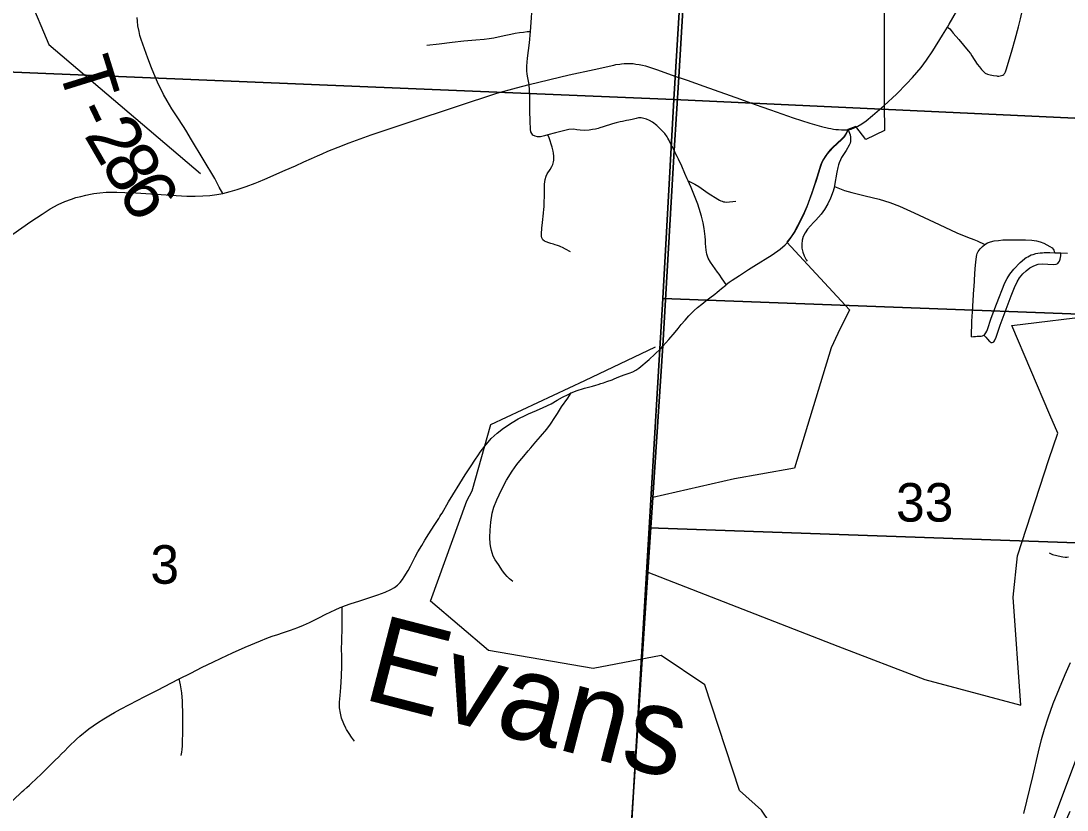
# Model space of a CAD drawing. Extents: x 21.4 to 65.3, y 4 to 26.
# Drawn here: x 25.81 to 26.947, y 22.714 to 23.571 of the extents above; entities that cross this region are included whole.
import ezdxf

# ---------------------------------------------------------------- set-up
doc = ezdxf.new("R2010")
doc.units = 0
for name, color, linetype in [('Default', 7, 'Continuous'), ('GM_X_City_Street', 7, 'Continuous'), ('GM_X_County_Road', 7, 'Continuous'), ('GM_X_Major_River', 7, 'Continuous'), ('GM_X_Minor_River', 7, 'Continuous'), ('GM_X_Minor_River_Text', 7, 'Continuous'), ('GM_X_Section', 7, 'Continuous'), ('GM_X_Section_Text', 7, 'Continuous'), ('GM_X_State_Route', 7, 'Continuous'), ('GM_X_Township_Road', 7, 'Continuous'), ('GM_X_Township_Road_Text', 7, 'Continuous')]:
    doc.layers.add(name, color=color, linetype=linetype)

msp = doc.modelspace()

# ---------------------------------------------------------------- linework, layer by layer
at = {"layer": 'Default'}
for points in [[(26.3906, 21.3613), (26.4573, 22.45), (26.4915, 22.9722), (26.4968, 23.0532), (26.5076, 23.2181), (26.5201, 23.4302), (26.5253, 23.5099), (26.571, 24.2838), (26.5714, 24.2916), (26.5716, 24.3007), (26.5721, 24.3116), (26.5728, 24.3278), (26.5729, 24.3421), (26.5729, 24.3464), (26.5731, 24.3575), (26.5731, 24.358), (26.5731, 24.3616), (26.5731, 24.3659), (26.5732, 24.3694), (26.5734, 24.3737), (26.5741, 24.3781), (26.6018, 24.8542), (23.5473, 24.8542), (23.5473, 20.5568)], [(29.9103, 24.8542), (26.6018, 24.8542), (26.5741, 24.3781), (26.5734, 24.3737), (26.5732, 24.3694), (26.5731, 24.3659), (26.5731, 24.3616), (26.5731, 24.358), (26.5731, 24.3575), (26.5729, 24.3464), (26.5729, 24.3421), (26.5728, 24.3278), (26.5721, 24.3116), (26.5716, 24.3007), (26.5714, 24.2916), (26.571, 24.2838), (26.5253, 23.5099), (26.5201, 23.4302), (26.5076, 23.2181), (26.4968, 23.0532), (26.4915, 22.9722), (26.4573, 22.45), (26.3906, 21.3613)], [(26.7486, 23.7813), (26.7481, 23.4797), (26.7485, 23.4518), (26.7284, 23.4422), (26.7174, 23.4563), (26.7088, 23.4531), (26.7075, 23.45), (26.706, 23.4473), (26.7052, 23.446), (26.7042, 23.4448), (26.7021, 23.4428), (26.6922, 23.4335), (26.6896, 23.4308), (26.6866, 23.4272), (26.6841, 23.4237), (26.6822, 23.4206), (26.6803, 23.4168), (26.6788, 23.4128), (26.677, 23.4068), (26.6744, 23.3986), (26.6695, 23.3839), (26.6644, 23.37), (26.6603, 23.3604), (26.6571, 23.354), (26.6542, 23.3482), (26.6505, 23.3415), (26.6467, 23.336), (26.6426, 23.3306), (26.7105, 23.2572), (26.6979, 23.2313), (26.6908, 23.216), (26.6508, 23.0851), (26.6144, 23.0787), (26.5855, 23.0736), (26.4968, 23.0532), (26.4915, 22.9722), (26.698, 22.8919), (26.7924, 22.8556), (26.8965, 22.8277), (26.8883, 22.9449), (26.8931, 22.9901), (26.9271, 23.0947), (26.9369, 23.1232), (26.928, 23.1431), (26.8869, 23.24), (26.9821, 23.2516)]]:
    msp.add_lwpolyline(points, dxfattribs=at)
at = {"layer": 'GM_X_City_Street'}
for points in [[(26.877, 23.5119), (26.8781, 23.5127), (26.8787, 23.5134), (26.8794, 23.5143), (26.88, 23.5158), (26.8808, 23.5179), (26.8823, 23.5225), (26.8873, 23.5397), (26.8906, 23.5512), (26.8943, 23.5645), (26.8963, 23.5731), (26.8994, 23.5875), (26.9034, 23.6082), (26.9059, 23.6222), (26.9076, 23.63), (26.9088, 23.6349), (26.9105, 23.6409), (26.9111, 23.6426), (26.9122, 23.6448), (26.9152, 23.6491)], [(26.8171, 23.5643), (26.8194, 23.5622), (26.8209, 23.5607), (26.8233, 23.5578), (26.8294, 23.5507), (26.8345, 23.5446), (26.8396, 23.5384), (26.8419, 23.5354), (26.8435, 23.533), (26.8493, 23.5239), (26.8516, 23.5209), (26.8538, 23.5182), (26.8556, 23.5162), (26.8578, 23.5143), (26.8605, 23.5131), (26.8633, 23.5122), (26.8669, 23.5115), (26.8705, 23.5112), (26.8715, 23.5111), (26.8726, 23.5111), (26.8741, 23.5113), (26.8755, 23.5115), (26.877, 23.5119)], [(26.709, 23.4526), (26.7112, 23.4471), (26.7116, 23.4448), (26.7118, 23.4422), (26.7116, 23.44), (26.7111, 23.4381), (26.7102, 23.436), (26.7068, 23.4303), (26.702, 23.4226), (26.7007, 23.4199), (26.6994, 23.4169), (26.6985, 23.4146), (26.6978, 23.4118), (26.6967, 23.4068), (26.6943, 23.3921), (26.6941, 23.3911), (26.6927, 23.3861), (26.69, 23.3785), (26.687, 23.3724), (26.6833, 23.366), (26.6797, 23.361), (26.6769, 23.3577), (26.674, 23.3545), (26.6714, 23.3518), (26.6651, 23.3449), (26.6623, 23.3408), (26.6603, 23.3369), (26.6591, 23.3328), (26.6586, 23.3284), (26.6588, 23.3241), (26.6597, 23.3198), (26.6612, 23.3158), (26.6635, 23.3114), (26.6644, 23.3101)], [(26.6941, 23.3911), (26.6998, 23.3889), (26.705, 23.3868), (26.7132, 23.3844), (26.7275, 23.3811), (26.7429, 23.3772), (26.7545, 23.3736), (26.7647, 23.3696), (26.7809, 23.3624), (26.8081, 23.3497), (26.827, 23.3409), (26.8389, 23.336), (26.8456, 23.3335), (26.8491, 23.3321), (26.8576, 23.3281), (26.8604, 23.3299), (26.8636, 23.3311), (26.8678, 23.3321), (26.8724, 23.3326), (26.8772, 23.333), (26.8901, 23.3332), (26.9019, 23.333), (26.9087, 23.3327), (26.9136, 23.3321), (26.9178, 23.3311), (26.9218, 23.3296), (26.9283, 23.326), (26.9306, 23.3244), (26.9319, 23.3229), (26.9325, 23.3218), (26.933, 23.3206), (26.9335, 23.3192)], [(26.8432, 23.2277), (26.8431, 23.2331), (26.8434, 23.2393), (26.8434, 23.2418), (26.8436, 23.2448), (26.8441, 23.2548), (26.8449, 23.2672), (26.8457, 23.2796), (26.8458, 23.2821), (26.8468, 23.2962), (26.8472, 23.3018), (26.8479, 23.3094), (26.8481, 23.3119), (26.8485, 23.3152), (26.8489, 23.317), (26.8494, 23.3184), (26.8503, 23.3203), (26.8526, 23.3235), (26.8549, 23.3259), (26.8576, 23.3281)], [(26.8432, 23.2277), (26.8453, 23.2281), (26.8473, 23.2283), (26.8491, 23.2284), (26.852, 23.2285), (26.8537, 23.2286), (26.855, 23.2289), (26.8563, 23.2296), (26.8571, 23.23), (26.858, 23.2309), (26.8588, 23.232), (26.8597, 23.2338), (26.8604, 23.2359), (26.8644, 23.2482), (26.8702, 23.2633), (26.8793, 23.2863), (26.8819, 23.2913), (26.8849, 23.296), (26.8892, 23.3013), (26.896, 23.3085), (26.8982, 23.3104), (26.901, 23.3128), (26.9025, 23.3138), (26.9041, 23.3148), (26.906, 23.3158), (26.908, 23.3167), (26.91, 23.3174), (26.9128, 23.3182), (26.9151, 23.3186), (26.9177, 23.319), (26.9201, 23.3192), (26.922, 23.3193), (26.9252, 23.3194), (26.9282, 23.3194), (26.9335, 23.3192), (26.94, 23.3189), (26.9474, 23.3187)], [(26.8563, 23.2296), (26.8585, 23.2273), (26.8603, 23.2253), (26.8628, 23.2226), (26.8634, 23.2222), (26.8642, 23.2218), (26.8649, 23.2216), (26.8656, 23.2216), (26.8665, 23.2219), (26.8674, 23.2225), (26.8679, 23.2233), (26.8684, 23.2243), (26.8698, 23.2273), (26.8741, 23.2403), (26.8806, 23.2577), (26.8862, 23.2722), (26.8899, 23.2814), (26.8928, 23.2876), (26.8954, 23.2918), (26.8989, 23.2962), (26.9024, 23.2996), (26.9064, 23.3027), (26.9107, 23.305), (26.9154, 23.3066), (26.9204, 23.3071), (26.926, 23.3069), (26.9322, 23.3064), (26.9352, 23.3068), (26.9369, 23.3076), (26.9377, 23.3084), (26.9387, 23.3099), (26.9394, 23.3122), (26.94, 23.3159), (26.94, 23.3189)]]:
    msp.add_lwpolyline(points, dxfattribs=at)
at = {"layer": 'GM_X_County_Road'}
for points in [[(26.6428, 23.33), (26.6469, 23.3354), (26.6507, 23.341), (26.6544, 23.3476), (26.6573, 23.3535), (26.6605, 23.3598), (26.6646, 23.3695), (26.6698, 23.3834), (26.6746, 23.3981), (26.6772, 23.4063), (26.679, 23.4122), (26.6805, 23.4163), (26.6824, 23.42), (26.6843, 23.4232), (26.6868, 23.4266), (26.6898, 23.4303), (26.6924, 23.433), (26.7023, 23.4422), (26.7044, 23.4443), (26.7054, 23.4455), (26.7062, 23.4468), (26.7077, 23.4495), (26.709, 23.4526)], [(26.5078, 23.2176), (26.5143, 23.2248), (26.521, 23.2327), (26.5243, 23.2369), (26.5278, 23.2412), (26.5319, 23.246), (26.536, 23.2506), (26.5393, 23.254), (26.5417, 23.2563), (26.5456, 23.2596), (26.5501, 23.2633), (26.5546, 23.2668), (26.559, 23.27), (26.5643, 23.2743), (26.5667, 23.2763), (26.569, 23.2783), (26.5714, 23.2802), (26.5761, 23.284), (26.5767, 23.2845), (26.5799, 23.287), (26.5832, 23.2894), (26.591, 23.2945), (26.6009, 23.3009), (26.6067, 23.3044), (26.6266, 23.317), (26.6351, 23.323), (26.6407, 23.3278), (26.6428, 23.33)], [(25.8016, 22.7243), (25.8118, 22.7338), (25.8137, 22.7355), (25.8168, 22.7384), (25.8196, 22.7408), (25.8228, 22.7438), (25.826, 22.7467), (25.8282, 22.7488), (25.8314, 22.7517), (25.8349, 22.7552), (25.8376, 22.7578), (25.841, 22.7613), (25.8441, 22.7643), (25.8476, 22.7679), (25.8512, 22.7713), (25.8545, 22.7749), (25.8581, 22.7783), (25.8615, 22.7819), (25.8652, 22.7852), (25.8683, 22.7883), (25.871, 22.7908), (25.8746, 22.7941), (25.8842, 22.8021), (25.8935, 22.8085), (25.9006, 22.8128), (25.9078, 22.8173), (25.912, 22.8197), (25.9187, 22.8234), (25.9283, 22.8286), (25.945, 22.8371), (25.959, 22.844), (25.9816, 22.8558), (25.9825, 22.8562), (25.9951, 22.8623), (26.0074, 22.8689), (26.0188, 22.8745), (26.0279, 22.8788), (26.0402, 22.8846), (26.0541, 22.8908), (26.0707, 22.8977), (26.0777, 22.9004), (26.0834, 22.9025), (26.0895, 22.9046), (26.0945, 22.9063), (26.1033, 22.9091), (26.1114, 22.912), (26.1173, 22.9146), (26.1239, 22.9174), (26.1297, 22.9204), (26.1349, 22.9231), (26.141, 22.9261), (26.1471, 22.9292), (26.1519, 22.9314), (26.1573, 22.9338), (26.1595, 22.9346), (26.1621, 22.9355), (26.1691, 22.938), (26.1777, 22.9408), (26.185, 22.9432), (26.198, 22.9474), (26.206, 22.9505), (26.2122, 22.9533), (26.2164, 22.9557), (26.2196, 22.9582), (26.2224, 22.961), (26.2248, 22.9642), (26.2269, 22.9671), (26.2311, 22.9739), (26.2337, 22.9788), (26.2387, 22.9888), (26.2417, 22.9943), (26.2458, 23.0012), (26.2494, 23.007), (26.2537, 23.0139), (26.2595, 23.0227), (26.2644, 23.0306), (26.2657, 23.0327), (26.2666, 23.0343), (26.2679, 23.0363), (26.275, 23.0486), (26.2795, 23.056), (26.2874, 23.0685), (26.293, 23.078), (26.2995, 23.0878), (26.3037, 23.094), (26.3074, 23.0997), (26.3095, 23.1027), (26.3144, 23.1092), (26.3214, 23.1172), (26.3278, 23.1232), (26.3347, 23.1286), (26.344, 23.1349), (26.3505, 23.1387), (26.359, 23.1428), (26.3618, 23.144), (26.3662, 23.146), (26.3704, 23.1476), (26.3779, 23.1511), (26.3866, 23.1552), (26.393, 23.1589), (26.3989, 23.1623), (26.405, 23.1653), (26.4081, 23.1668), (26.4094, 23.1674), (26.4138, 23.1691), (26.4226, 23.172), (26.4314, 23.1743), (26.4351, 23.1752), (26.4376, 23.176), (26.4405, 23.177), (26.4434, 23.1779), (26.4469, 23.1792), (26.4526, 23.1812), (26.4549, 23.1822), (26.4601, 23.1842), (26.4658, 23.1864), (26.4711, 23.1884), (26.4753, 23.1899), (26.4784, 23.1916), (26.4816, 23.1936), (26.493, 23.2033), (26.5051, 23.2146), (26.5078, 23.2176)]]:
    msp.add_lwpolyline(points, dxfattribs=at)
at = {"layer": 'GM_X_Major_River'}
msp.add_lwpolyline([(27.3721, 23.3957), (27.3499, 23.3785), (27.3039, 23.3339), (27.2682, 23.2939), (27.2227, 23.2357), (27.187, 23.179), (27.1419, 23.1192), (27.1141, 23.0781), (27.1024, 23.0556), (27.062, 22.9659), (27.006, 22.873), (26.973, 22.8129), (26.9266, 22.6893), (26.8772, 22.5703), (26.8597, 22.503), (26.8575, 22.4909), (26.8322, 22.3833), (26.828, 22.3063), (26.8227, 22.1096)], dxfattribs=at)
at = {"layer": 'GM_X_Minor_River'}
for points in [[(25.8194, 23.5963), (25.8409, 23.5452), (26.0056, 23.4051)], [(26.8808, 22.5795), (26.8755, 22.5813), (26.827, 22.5456), (26.8241, 22.5695), (26.7757, 22.6089), (26.7538, 22.6), (26.746, 22.5889), (26.6714, 22.63), (26.6149, 22.7137), (26.5911, 22.7352), (26.5535, 22.8498), (26.506, 22.8817), (26.4322, 22.8677), (26.3184, 22.8872), (26.2554, 22.9406), (26.295, 23.0495), (26.3006, 23.0605), (26.3209, 23.1324), (26.4231, 23.1804), (26.4997, 23.2168)]]:
    msp.add_lwpolyline(points, dxfattribs=at)
at = {"layer": 'GM_X_Section'}
for points in [[(26.5825, 24.5101), (26.5198, 23.4854), (25.4788, 23.5287), (25.4893, 23.7114), (25.5145, 24.1345), (25.5389, 24.555)], [(26.5825, 24.5101), (27.6091, 24.4648), (27.5486, 23.5443), (27.5415, 23.5386), (27.5313, 23.5298), (27.5214, 23.5207), (27.5097, 23.5112), (27.4908, 23.4937), (27.4682, 23.4724), (27.4508, 23.456), (27.444, 23.4496), (27.4376, 23.4427), (26.5198, 23.4854)], [(25.4788, 23.5287), (26.5198, 23.4854), (26.5078, 23.2694), (26.4931, 23.0203), (26.4742, 22.7032), (26.4597, 22.4573), (25.4085, 22.5025), (25.4647, 23.2936)], [(26.5198, 23.4854), (27.4376, 23.4427), (27.4251, 23.4336), (27.4176, 23.4283), (27.3873, 23.4073), (27.3756, 23.3925), (27.3511, 23.3712), (27.3311, 23.3548), (27.311, 23.3339), (27.2963, 23.3195), (27.285, 23.3081), (27.2756, 23.2944), (27.2654, 23.2773), (27.256, 23.2621), (27.2435, 23.2454), (27.2404, 23.2418), (26.5078, 23.2694)], [(27.2404, 23.2418), (27.2326, 23.2325), (27.2118, 23.2108), (27.1948, 23.1911), (27.1767, 23.1683), (27.1658, 23.1508), (27.1552, 23.1356), (27.1466, 23.1231), (27.1394, 23.1121), (27.133, 23.0999), (27.1266, 23.0851), (27.124, 23.0768), (27.1153, 23.0642), (27.1059, 23.0475), (27.098, 23.0255), (27.0935, 23.0107), (27.0913, 22.9992), (26.4931, 23.0203), (26.5078, 23.2694)]]:
    msp.add_lwpolyline(points, close=True, dxfattribs=at)
msp.add_lwpolyline([(26.9498, 22.7121), (26.9438, 22.698), (26.9387, 22.6861), (26.4742, 22.7032), (26.4931, 23.0203), (27.0913, 22.9992)], dxfattribs=at)
at = {"layer": 'GM_X_State_Route'}
for points in [[(26.7483, 23.4792), (26.7616, 23.4915), (26.773, 23.5031), (26.779, 23.5094), (26.7838, 23.515), (26.7883, 23.5203), (26.7943, 23.5283), (26.8012, 23.5383), (26.8117, 23.5553), (26.8171, 23.5643), (26.8188, 23.5673), (26.8322, 23.5904)], [(26.0687, 23.3962), (26.0754, 23.399), (26.0975, 23.4089), (26.1086, 23.4137), (26.1179, 23.4178), (26.1262, 23.4215), (26.1327, 23.4243), (26.1378, 23.4266), (26.144, 23.4293), (26.155, 23.4337), (26.1669, 23.4386), (26.1908, 23.4472), (26.231, 23.4605), (26.2846, 23.4785), (26.3276, 23.4924), (26.3489, 23.4984), (26.3627, 23.502), (26.406, 23.5122), (26.433, 23.5183), (26.4544, 23.523), (26.4568, 23.5235), (26.4609, 23.5241), (26.4628, 23.5243), (26.4659, 23.5246), (26.4693, 23.5248), (26.4725, 23.5247), (26.4754, 23.5246), (26.4786, 23.5241), (26.4821, 23.5237), (26.4856, 23.5229), (26.4889, 23.522), (26.4987, 23.5189), (26.502, 23.5178), (26.5249, 23.5096), (26.5255, 23.5094)], [(26.5255, 23.5094), (26.5341, 23.5064), (26.5524, 23.4999), (26.592, 23.4858), (26.603, 23.4819), (26.6153, 23.4775), (26.6246, 23.4742), (26.6493, 23.4658), (26.6674, 23.4598), (26.6801, 23.4563), (26.6877, 23.4544), (26.6904, 23.4539), (26.693, 23.4535), (26.6958, 23.4531), (26.6986, 23.4529), (26.7017, 23.4527), (26.7052, 23.4525), (26.709, 23.4526)], [(26.7285, 23.4623), (26.7356, 23.4681), (26.7483, 23.4792)], [(26.709, 23.4526), (26.7122, 23.4535), (26.7156, 23.4548), (26.7196, 23.4566), (26.724, 23.4591), (26.7285, 23.4623)], [(25.8018, 23.3394), (25.8212, 23.353), (25.8334, 23.3611), (25.8421, 23.3668), (25.851, 23.3714), (25.8583, 23.3747), (25.8653, 23.3773), (25.8702, 23.379), (25.8754, 23.3803), (25.8808, 23.3816), (25.8859, 23.3826), (25.8898, 23.3833), (25.8962, 23.3842), (25.9029, 23.3848), (25.908, 23.3849), (25.9146, 23.385), (25.9233, 23.3847), (25.9352, 23.3841), (25.9791, 23.3812), (25.9907, 23.3806), (25.9998, 23.3805), (26.008, 23.3808), (26.0158, 23.3814), (26.0233, 23.3823), (26.0297, 23.3835), (26.0378, 23.3855), (26.0454, 23.3877), (26.0551, 23.391), (26.0649, 23.3947), (26.0687, 23.3962)], [(26.8999, 22.7099), (26.9096, 22.7504), (26.9158, 22.777), (26.9193, 22.7903), (26.9225, 22.8017), (26.9264, 22.8141), (26.9319, 22.8294), (26.9386, 22.8461), (26.9449, 22.861), (26.9507, 22.8741)]]:
    msp.add_lwpolyline(points, dxfattribs=at)
at = {"layer": 'GM_X_Township_Road'}
for points in [[(26.3627, 23.502), (26.3608, 23.5108), (26.3604, 23.5136), (26.3601, 23.5165), (26.3601, 23.5192), (26.3602, 23.5219), (26.3609, 23.5303), (26.3629, 23.5471), (26.364, 23.5595), (26.365, 23.5743), (26.3658, 23.586), (26.3667, 23.6027), (26.3677, 23.6212)], [(25.9896, 23.4521), (25.987, 23.4564), (25.9802, 23.4668), (25.9745, 23.4756), (25.9693, 23.4841), (25.9654, 23.4911), (25.9589, 23.5045), (25.9566, 23.5096), (25.9523, 23.5199), (25.9484, 23.5303), (25.9465, 23.5355), (25.9412, 23.5507), (25.9398, 23.5552), (25.9388, 23.5595), (25.9376, 23.5656), (25.9371, 23.5706), (25.9368, 23.5745)], [(26.2515, 23.5446), (26.2649, 23.5461), (26.2788, 23.5478), (26.2917, 23.5492), (26.3046, 23.5503), (26.3137, 23.551), (26.319, 23.5517), (26.3242, 23.5526), (26.3355, 23.5551), (26.3392, 23.5559), (26.3427, 23.5567), (26.3472, 23.5575), (26.3521, 23.5583), (26.3565, 23.5588), (26.3605, 23.5593), (26.364, 23.5595)], [(26.5204, 23.4297), (26.5178, 23.4345), (26.5162, 23.4379), (26.5143, 23.4417), (26.5132, 23.4437), (26.5123, 23.4452), (26.5098, 23.4486), (26.5073, 23.4513), (26.5011, 23.4572), (26.4964, 23.461), (26.4933, 23.4629), (26.4901, 23.4643), (26.4873, 23.4651), (26.4844, 23.4656), (26.4815, 23.4655), (26.4787, 23.4649), (26.4746, 23.4639), (26.471, 23.4632), (26.4683, 23.4627), (26.4655, 23.4622), (26.4638, 23.4618), (26.4614, 23.4614), (26.4571, 23.4601), (26.4532, 23.459), (26.4431, 23.4558), (26.4395, 23.4547), (26.4377, 23.4542), (26.4347, 23.4535), (26.4315, 23.4529), (26.4279, 23.4523), (26.4228, 23.452), (26.4178, 23.4523), (26.4143, 23.4528), (26.411, 23.4532), (26.4057, 23.453), (26.3997, 23.4517), (26.3913, 23.4495), (26.3829, 23.4471), (26.3793, 23.446), (26.3749, 23.4452), (26.3716, 23.4451), (26.369, 23.4457), (26.3666, 23.447), (26.3653, 23.4486), (26.3644, 23.4504), (26.3639, 23.4531), (26.3635, 23.4623), (26.3633, 23.4729), (26.3634, 23.4901), (26.3627, 23.502)], [(26.0297, 23.3835), (26.0259, 23.3905), (26.021, 23.3996), (26.0085, 23.4208), (25.9959, 23.4417), (25.9896, 23.4521)], [(26.4074, 23.32), (26.4022, 23.323), (26.3987, 23.3248), (26.3971, 23.3256), (26.3954, 23.3262), (26.3943, 23.3265), (26.3932, 23.3269), (26.3909, 23.3277), (26.3891, 23.3283), (26.3874, 23.3288), (26.3862, 23.3292), (26.3839, 23.3298), (26.381, 23.3309), (26.3793, 23.3318), (26.3775, 23.3333), (26.3762, 23.3353), (26.3759, 23.3371), (26.3758, 23.3395), (26.3765, 23.3457), (26.377, 23.3518), (26.3782, 23.3622), (26.3786, 23.3665), (26.3787, 23.3689), (26.3789, 23.3739), (26.3791, 23.3807), (26.3792, 23.3869), (26.3794, 23.3937), (26.3795, 23.3962), (26.3799, 23.3986), (26.381, 23.4022), (26.3823, 23.405), (26.3854, 23.4096), (26.3873, 23.4128), (26.3883, 23.4151), (26.3888, 23.4165), (26.3891, 23.418), (26.3893, 23.4198), (26.3893, 23.4217), (26.3892, 23.4242), (26.3889, 23.4272), (26.3885, 23.4296), (26.3875, 23.4337), (26.3865, 23.4372), (26.3854, 23.4407), (26.3843, 23.4438), (26.3829, 23.4471)], [(26.5767, 23.2845), (26.5724, 23.2907), (26.569, 23.2957), (26.5672, 23.2982), (26.5597, 23.3089), (26.5572, 23.3133), (26.5556, 23.3175), (26.5547, 23.3218), (26.5543, 23.3293), (26.5541, 23.3329), (26.5538, 23.3366), (26.5535, 23.3396), (26.5527, 23.3456), (26.5515, 23.3516), (26.5498, 23.3588), (26.5473, 23.3671), (26.5458, 23.3718), (26.5422, 23.381), (26.5385, 23.3901), (26.5367, 23.394), (26.5352, 23.3972), (26.5341, 23.3994), (26.5316, 23.4052), (26.5283, 23.413), (26.5247, 23.4208), (26.5234, 23.4236), (26.5217, 23.4269), (26.5204, 23.4297)], [(26.5352, 23.3972), (26.5403, 23.3947), (26.5424, 23.3937), (26.5468, 23.3909), (26.5571, 23.3839), (26.5676, 23.3772), (26.5693, 23.3763), (26.5709, 23.3755), (26.5723, 23.3751), (26.5738, 23.3746), (26.5752, 23.3743), (26.5769, 23.3742), (26.5869, 23.3752)], [(26.3215, 22.9956), (26.3208, 22.9991), (26.3203, 23.0028), (26.3199, 23.0097), (26.3201, 23.0177), (26.3209, 23.0264), (26.3225, 23.0362), (26.3243, 23.0428), (26.3274, 23.0509), (26.3324, 23.0616), (26.338, 23.072), (26.3441, 23.082), (26.3492, 23.0891), (26.3526, 23.0932), (26.3567, 23.0981), (26.3616, 23.1038), (26.3643, 23.1072), (26.3699, 23.1137), (26.375, 23.1197), (26.3816, 23.1274), (26.3858, 23.1328), (26.3904, 23.1402), (26.3932, 23.1446), (26.3977, 23.1517), (26.4044, 23.1613), (26.4081, 23.1668)], [(26.3447, 22.962), (26.3411, 22.9649), (26.3387, 22.9673), (26.3362, 22.9702), (26.3335, 22.9738), (26.3292, 22.9804), (26.3258, 22.9854), (26.3236, 22.9897), (26.3222, 22.9933), (26.3215, 22.9956)], [(26.9274, 22.9932), (26.9289, 22.9923), (26.9311, 22.9915), (26.9406, 22.9893), (26.9424, 22.9889), (26.9449, 22.9885), (26.9467, 22.9886), (26.9485, 22.989)], [(26.1727, 22.7887), (26.1697, 22.793), (26.1672, 22.7968), (26.1655, 22.7993), (26.1642, 22.8012), (26.1634, 22.8028), (26.1612, 22.8073), (26.1588, 22.8137), (26.1575, 22.8191), (26.1567, 22.8247), (26.1566, 22.8309), (26.1571, 22.8383), (26.1578, 22.8469), (26.1588, 22.8593), (26.1589, 22.8706), (26.1591, 22.8803), (26.1588, 22.8896), (26.159, 22.8963), (26.1596, 22.9136), (26.1596, 22.9279), (26.1595, 22.9346)], [(25.9846, 22.7732), (25.9853, 22.7766), (25.9857, 22.7797), (25.986, 22.7834), (25.9864, 22.8022), (25.9865, 22.8164), (25.9861, 22.8319), (25.9853, 22.8412), (25.9837, 22.8497), (25.9825, 22.8562)]]:
    msp.add_lwpolyline(points, dxfattribs=at)

# ---------------------------------------------------------------- texts
at = {"layer": 'GM_X_Minor_River_Text'}
msp.add_text('Evans', height=0.0947, rotation=345.5114, dxfattribs=at).set_placement((26.1799, 22.8349))
at = {"layer": 'GM_X_Section_Text'}
for s, height, p in [('33', 0.04186, (26.7611, 23.0271)), ('3', 0.0419, (25.9511, 22.9596))]:
    msp.add_text(s, height=height, rotation=0, dxfattribs=at).set_placement(p)
at = {"layer": 'GM_X_Township_Road_Text'}
for s, rotation, p in [('T', 287.2883, (25.8502, 23.5213)), ('-', 295.5151, (25.866, 23.4725)), ('2', 300.1787, (25.8784, 23.4469)), ('8', 300.8467, (25.8964, 23.4161)), ('6', 301.0714, (25.9145, 23.3858))]:
    msp.add_text(s, height=0.0568, rotation=rotation, dxfattribs=at).set_placement(p)

doc.saveas('drawing.dxf')
